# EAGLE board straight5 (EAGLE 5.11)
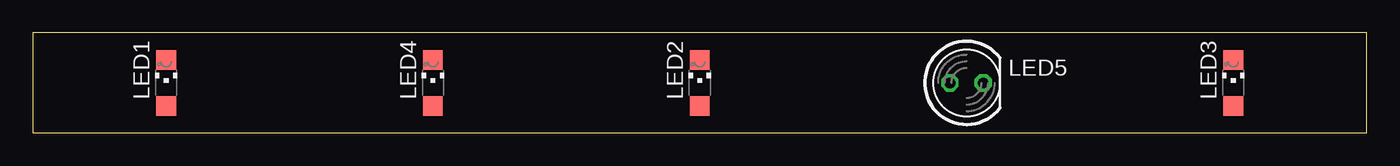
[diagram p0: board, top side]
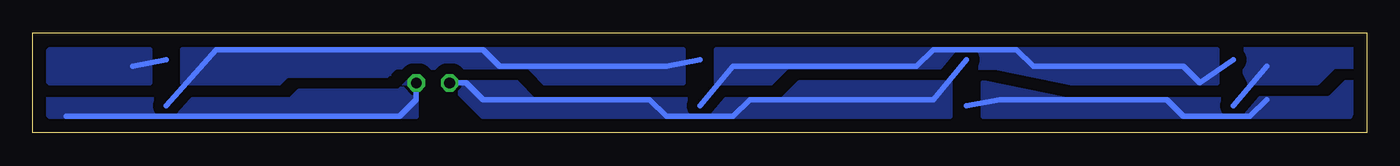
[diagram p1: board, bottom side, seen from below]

Size 101.6 x 7.62 mm. Coordinates in mm from the lower left corner, seen from the top.
Outline: 0,0 101.6,0 101.6,7.62 0,7.62 0,0
Copper layers (1*16): Top 0.035mm / dielectric 1.5mm / Bottom 0.035mm
Design rules "default": minimum track width 10mil, minimum drill 24mil, track to track 8mil, track to pad 8mil, pad to pad 8mil, via to via 8mil, smd to smd 8mil, copper to edge 40mil, drill to drill 8mil, minimum pad ring 10mil, minimum via ring 8mil, stop-mask expansion 4mil, vias tented up to drill 0mil, thermal gap 10mil

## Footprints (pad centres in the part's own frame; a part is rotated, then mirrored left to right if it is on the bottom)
CHIPLED_1206 = smd 1.5 x 1.5: A 0,-1.75; C 0,1.75
LED5MM = drill 0.813 octagon: A -1.27,0; K 1.27,0

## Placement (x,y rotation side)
LED1  [CHIPLED_1206]  10.16,3.81 0 top
LED2  [CHIPLED_1206]  50.8,3.81 0 top
LED3  [CHIPLED_1206]  91.44,3.81 0 top
LED4  [CHIPLED_1206]  30.48,3.81 0 top
LED5  [LED5MM]  71.12,3.81 0 top

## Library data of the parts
LED1-LED5 = led

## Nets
N$1: LED1.A
N$2: LED1.C LED2.A
N$3: LED2.C LED3.A
N$4: LED3.C
N$5: LED4.A
N$6: LED4.C LED5.A
N$7: LED5.K

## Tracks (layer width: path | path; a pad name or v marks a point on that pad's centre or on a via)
N$1
  Bottom 0.406: LED1.A 7.62,5.08
  pour Bottom (isolate 0.813): 0,5.08 0,6.35 10.16,6.35 8.89,3.81 3.81,3.81 2.54,5.08
N$2
  Bottom 0.406: LED1.C 12.7,3.81 13.97,5.08 25.4,5.08 26.67,6.35 33.02,6.35 34.29,5.08 48.26,5.08 LED2.A
  pour Bottom (isolate 0.813, rank 3): 11.43,3.81 11.43,6.35 49.53,6.35 49.53,3.81 13.97,3.81
N$3
  Bottom 0.406: LED2.C 53.34,5.08 66.04,5.08 67.31,6.35 87.63,6.35 LED3.A
  pour Bottom (isolate 0.813, rank 3): 52.07,3.81 52.07,6.35 90.17,6.35 90.17,3.81 53.34,3.81
N$4
  Bottom 0.406: LED3.C 93.98,5.08
  pour Bottom (isolate 0.813, rank 3): 92.71,3.81 92.71,6.35 100.33,6.35 101.6,5.08 100.33,3.81
N$5
  Bottom 0.406: LED4.A 27.94,2.54 15.24,2.54 13.97,1.27 8.89,1.27 7.62,2.54
  pour Bottom (isolate 0.813, rank 2): 0,3.81 7.62,3.81 10.16,2.54 22.86,2.54 29.21,3.81 29.21,1.27 1.27,1.27
N$6
  Bottom 0.406: LED5.A 68.58,3.81 67.31,2.54 54.61,2.54 53.34,1.27 48.26,1.27 46.99,2.54 33.02,2.54 LED4.C
  pour Bottom (isolate 0.813, rank 2): 31.75,3.81 31.75,1.27 67.31,1.27 69.85,3.81 64.77,3.81 63.5,2.54 44.45,2.54 43.18,3.81
N$7
  Bottom 0.406: LED5.K 72.39,2.54 73.66,1.27 99.06,1.27
  pour Bottom (isolate 0.813, rank 2): 72.39,3.81 72.39,1.27 100.33,1.27 101.6,2.54 81.92,2.54 81.28,3.17 73.66,3.17 73.03,3.81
